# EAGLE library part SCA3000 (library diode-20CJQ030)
VTI's SCA3000 (-D01, -D02, -E02, -E04) 3-AXIS ULTRA LOW POWER ACCELEROMETER WITH DIGITAL I2C or SPI INTERFACE Description: SCA3000 is a three axis accelerometer family targeted for products requiring high performance with low power consumption. It consists of a 3D-MEMS sensing element and a signal conditioning ASIC packaged into a plastic Molded Interconnection Device package (MID). Features: 2.35 V - 3.6 V supply voltage, 1.7 V - 3.6 V digital I/O voltage ±2 g, ±3 g or ±6 g measurement range I2C or SPI digital interface: V2.1 compliant, 10-bit addressing, supports standard mode Selectable frequency response Ultra low current consumption (2.5 V, 120 uA, 200 uA, 480 uA or 650 uA typ) 64 samples/axis buffer memory for output acceleration data and advanced features enable significant power and resource savings at system level Interrupt signal triggered by motion and free fall Size 7x7x1.8 mm Proven capacitive 3D-MEMS technology High shock durability RoHS compliant / lead free soldering Applications: SCA3000-E02 is targeted to battery operated wrist and hand-held devices. Typical applications are but not limited Motion activated functions in mobile terminals and antitheft systems Gaming input devices Inclination sensing in digital inclinometers Tilt compensation in electronic compass Hard disk protection Pedometers and activity monitors Please send any comments to: messi@users.sourceforge.net
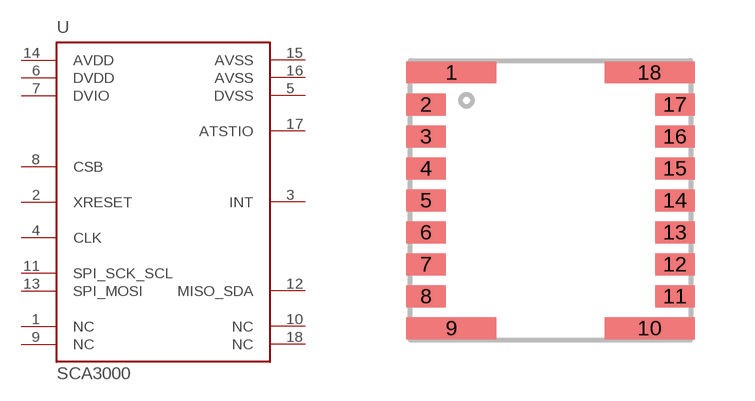
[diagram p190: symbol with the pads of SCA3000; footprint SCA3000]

Designator prefix U

## SCA3000  [SCA3000]
1  NC  nc
2  XRESET  in
3  INT  out
4  CLK  in
5  DVSS  pwr
6  DVDD  pwr
7  DVIO  pwr
8  CSB  in
9  NC  nc
10  NC  nc
11  SPI_SCK_SCL  in
12  MISO_SDA
13  SPI_MOSI  in
14  AVDD  pwr
15  AVSS  pwr
16  AVSS  pwr
17  ATSTIO  pas
18  NC  nc

## Footprint SCA3000 (pad centres in mm)
VTI's landpattern for the SCA3000 accelerometer
smd 2.25 x 0.55: 1 -2.475,3.2; 9 -2.475,-3.2; 10 2.475,-3.2; 18 2.475,3.2
smd 0.976 x 0.55: 2 -3.112,2.4; 3 -3.112,1.6; 4 -3.112,0.8; 5 -3.112,0; 6 -3.112,-0.8; 7 -3.112,-1.6; 8 -3.112,-2.4; 11 3.112,-2.4; 12 3.112,-1.6; 13 3.112,-0.8; 14 3.112,0; 15 3.112,0.8; 16 3.112,1.6; 17 3.112,2.4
